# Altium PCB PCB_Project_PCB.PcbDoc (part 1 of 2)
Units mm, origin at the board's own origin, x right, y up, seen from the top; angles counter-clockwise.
Board outline 177.8 x 50.8 mm, 4 copper layers (Top Layer, Signal Layer 1, Signal Layer 2, Bottom Layer), stack 1.016 mm thick; 119 components, 90 nets, 392 pads, 439 vias.
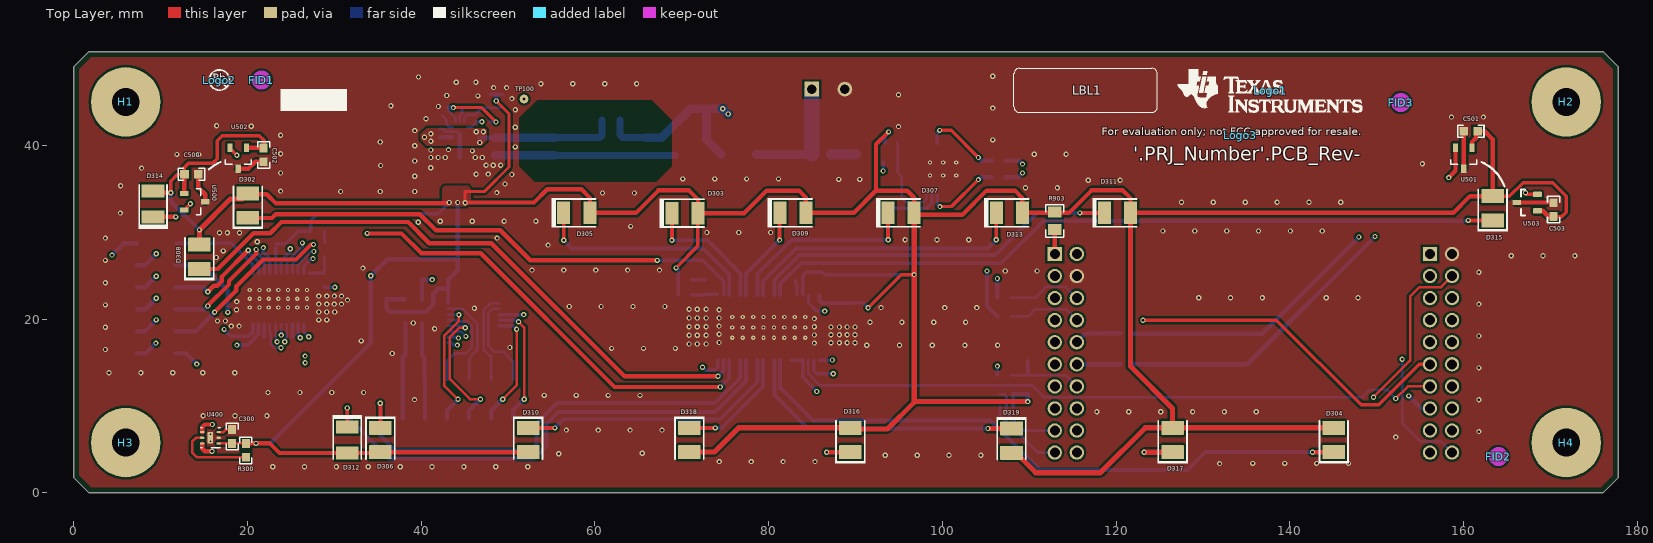
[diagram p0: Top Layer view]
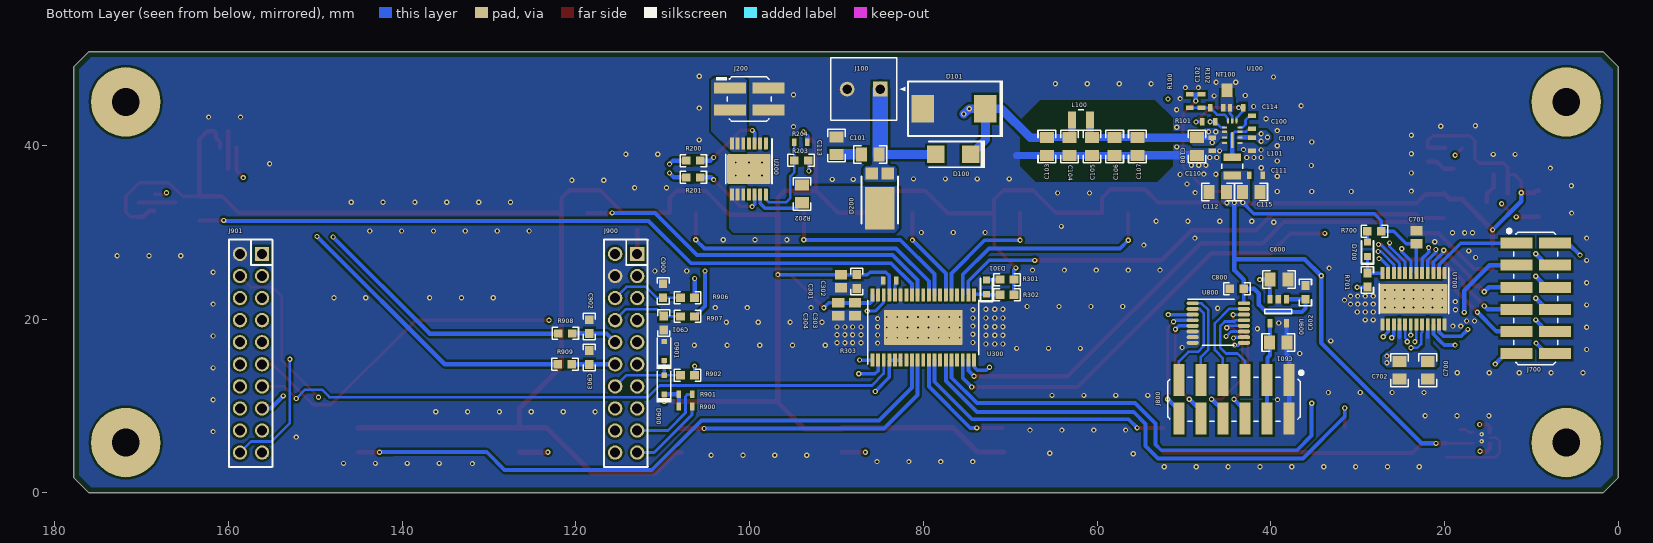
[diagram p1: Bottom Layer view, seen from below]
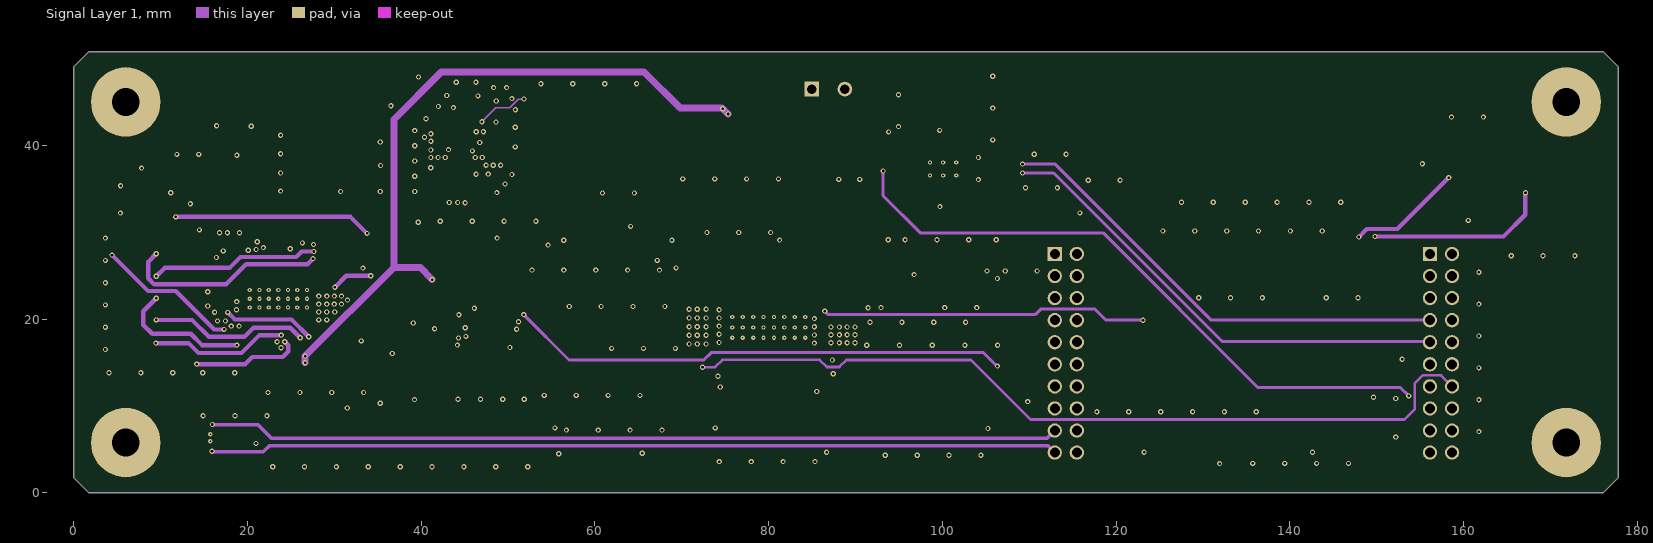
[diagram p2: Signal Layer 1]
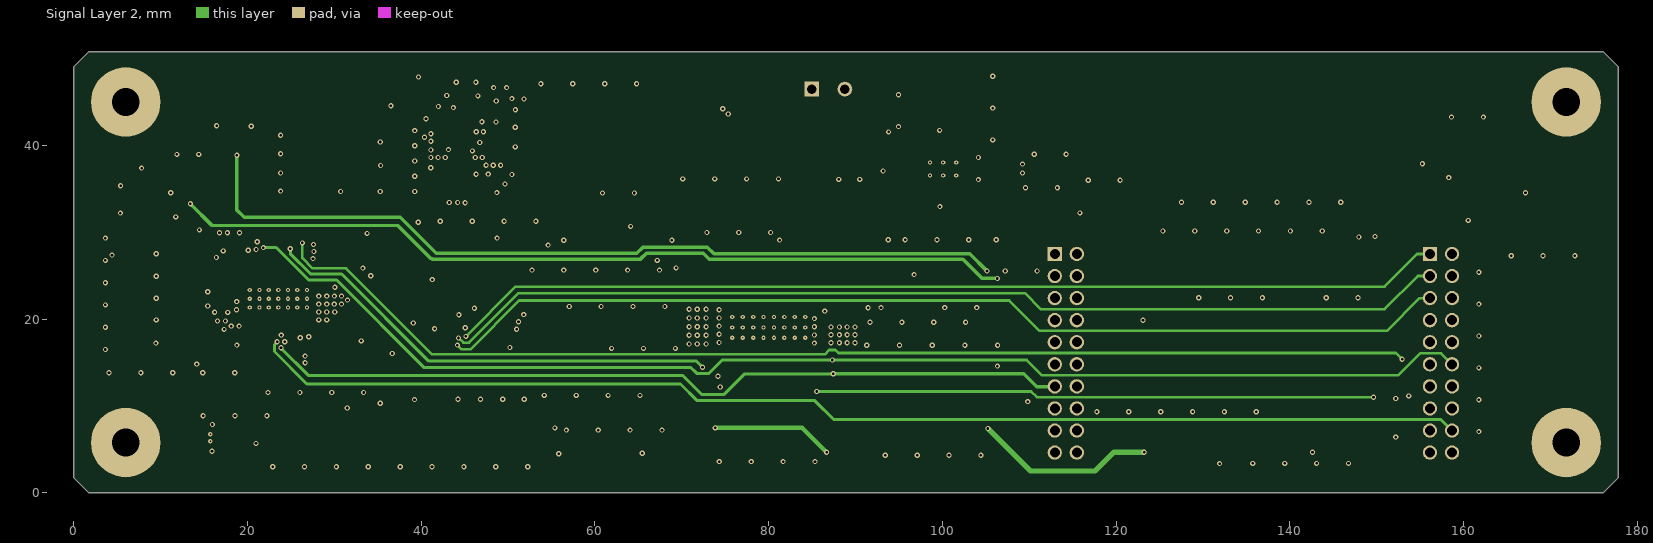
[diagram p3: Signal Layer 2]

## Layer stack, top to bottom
Top Solder: solder mask 0.0102, Solder Resist, Dk 3.5
Top Layer: signal copper 0.0356
Dielectric 2: prepreg 0.127, FR-4, Dk 4.2
Signal Layer 1: signal copper 0.0356
Dielectric 3: core 0.6198, FR-4, Dk 4.2
Signal Layer 2: signal copper 0.0356
Dielectric1: prepreg 0.127, FR-4, Dk 4.2
Bottom Layer: signal copper 0.0356
Bottom Solder: solder mask 0.0102, Solder Resist, Dk 3.5

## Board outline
0,1.778 0,49.022 1.778,50.8 176.022,50.8 177.8,49.022 177.8,1.778 176.022,0 1.778,0

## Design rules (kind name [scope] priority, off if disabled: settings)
AcuteAngle [All] p1: minimum=4.50000000000000E+0001 checktracksonly=FALSE
AssemblyTestPointUsage [All] p1: valid=2
BoardOutlineClearance BoardOutlineClearance_MountingHoles [OnCopper and InComponentClass('Mounting Holes')] p1: gap=1.016 ignorepadtopadclearanceinfootprint=FALSE
BoardOutlineClearance BoardOutlineClearance_Poly [OnCopper and IsPoly] p2: gap=0.635 ignorepadtopadclearanceinfootprint=FALSE
BoardOutlineClearance [OnCopper and Not InComponentClass('Logo') and not InComponentClass('FiducialMark') and not InRegion(1000,500,4000,800) and not InPoly] p3: gap=1.905 ignorepadtopadclearanceinfootprint=FALSE
Clearance "Stitching GND" [IsStitchingVia and InNet('GND') vs (IsVia and (Not IsStitchingVia)) Or IsPad] p1: gap=0.127 ignorepadtopadclearanceinfootprint=FALSE
Clearance Clearance_Keepouts [((IsTrack Or IsArc) And Not InPoly) And IsFree and IsKeepOut vs ((IsTrack Or IsArc) And Not InPoly) And IsFree and IsKeepOut] p2: gap=0 ignorepadtopadclearanceinfootprint=FALSE
Clearance Clearance_Poly [InPolygon] p3: gap=0.25 ignorepadtopadclearanceinfootprint=FALSE
Clearance Clearance_FiducialMark [IsKeepOut and InComponentClass('FiducialMark') vs IsPad and InComponentClass('FiducialMark')] p4: gap=0 ignorepadtopadclearanceinfootprint=FALSE
Clearance [All] p5: gap=0.2 ignorepadtopadclearanceinfootprint=FALSE except(0: Arc-Hole Track-Hole SMDPad-Hole THPad-Hole Via-Hole Fill-Hole Poly-Hole Region-Hole Text-Hole)
ComponentClearance ComponentClearance_MountingHoles_FiducialMarks [InComponentClass('Mounting Holes') vs InComponentClass('FiducialMark')] p1: gap=1.27 collisioncheckmode=3 verticalgap=0.254 showdistances=FALSE
ComponentClearance ComponentClearance_Shunt [InComponentClass('Header') vs InComponentClass('Shunt')] p2: gap=0 collisioncheckmode=3 verticalgap=0 showdistances=FALSE
ComponentClearance ComponentClearance_Logo [InComponentClass('Logo')] p3: gap=1.27 collisioncheckmode=3 verticalgap=0.254 showdistances=FALSE
ComponentClearance ComponentClearance_ScrewToNut [(HasFootprint('NY PMS 440 0025 PH')) vs (HasFootprint('Keystone_1902C'))] p4: gap=0.127 collisioncheckmode=3 verticalgap=0.254 showdistances=FALSE
ComponentClearance ComponentClearance_MountingHoles [InComponentClass('Mounting Holes')] p5: gap=6.35 collisioncheckmode=3 verticalgap=2540 showdistances=FALSE
ComponentClearance ComponentClearance_SmallPassives [HasFootprint('0201*') or HasFootprint('0402*') or HasFootprint('0508') or HasFootprint('0603*') or HasFootprint('0612') or HasFootprint('0805*') or HasFootprint('0815*') or HasFootprint('0830*') or HasFootprint('1206*') or HasFootprint('1210*') or HasFootprint('1808*') or HasFootprint('1812*') or HasFootprint('1825*') or HasFootprint('2010*') or HasFootprint('2220*') or HasFootprint('2225*') or HasFootprint('2512*') or HasFootprint('2728*') or HasFootprint('3518*') vs HasFootprint('0201*') or HasFootprint('0402*') or HasFootprint('0508') or HasFootprint('0603*') or HasFootprint('0612') or HasFootprint('0805*') or HasFootprint('0815*') or HasFootprint('0830*') or HasFootprint('1206*') or HasFootprint('1210*') or HasFootprint('1808*') or HasFootprint('1812*') or HasFootprint('1825*') or HasFootprint('2010*') or HasFootprint('2220*') or HasFootprint('2225*') or HasFootprint('2512*') or HasFootprint('2728*') or HasFootprint('3518*')] p6: gap=0.38 collisioncheckmode=3 verticalgap=0.254 showdistances=FALSE
ComponentClearance ComponentClearance_THtoSMT [IsThruComponent vs IsSMTComponent] p7: gap=1.016 collisioncheckmode=3 verticalgap=0.762 showdistances=FALSE
ComponentClearance ComponentClearance_THtoTH [IsThruComponent vs IsThruComponent] p8: gap=0.762 collisioncheckmode=3 verticalgap=0.762 showdistances=FALSE
ComponentClearance [All] p9: gap=0.762 collisioncheckmode=3 verticalgap=0.254 showdistances=FALSE
DiffPairsRouting [All] p1: maxlimit=2.54 minlimit=0.254 mostfreqgap=0.254 toplayer_minwidth=0.381 toplayer_maxwidth=0.381 toplayer_prefwidth=0.381 midlayer1_minwidth=0.381 midlayer1_maxwidth=0.381 midlayer1_prefwidth=0.381 midlayer2_minwidth=0.381 midlayer2_maxwidth=0.381 midlayer2_prefwidth=0.381 bottomlayer_minwidth=0.381 bottomlayer_maxwidth=0.381 bottomlayer_prefwidth=0.381 maxuncoupledlength=25.4
FabricationTestPointUsage TestPointUsage [All] p1: valid=2 allowmultiple=FALSE
FabricationTestpoint Testpoint [All] p1: side=3 testpointundercomponent=TRUE minsize=1.016 maxsize=2.54 preferedsize=1.524 minholesize=0 maxholesize=1.016 preferedholesize=0.813 testpointgrid=0.025 allowsidetop=TRUE allowsidebottom=TRUE usegrid=TRUE gridtolerance=0
FanoutControl Fanout_LCC [IsLCC] p1: bgadir=Out bgaviamode=Centered fanoutstyle=Auto fanoutdirection=Alternating viagrid=0.025 // Fanout_LCC (Default Rule)
FanoutControl Fanout_BGA [IsBGA] p2: bgadir=Out bgaviamode=Centered fanoutstyle=Auto fanoutdirection=Alternating viagrid=0.025 // Fanout_BGA (Default Rule)
FanoutControl Fanout_Default [All] p4: bgadir=Out bgaviamode=Centered fanoutstyle=Auto fanoutdirection=Alternating viagrid=0.025 // Fanout_Default (Default Rule)
FanoutControl Fanout_Small [(CompPinCount < 5)] p5: bgadir=Out bgaviamode=Centered fanoutstyle=Auto fanoutdirection=OutThenIn viagrid=0.025 // Fanout_Small (Default Rule)
HoleSize [All] p1: absolutevalues=TRUE maxlimit=6.375 minlimit=0.2 maxpercent=80.000 minpercent=20.000
MinimumAnnularRing MinimumAnnularRing_ThermalPadVias [IsVia and InAnyComponent] p1: minimumring=0.15
MinimumAnnularRing [All] p2: minimumring=0.15
MinimumSolderMaskSliver MinimumSolderMaskSliver_Logo [InComponentClass('Logo') vs InComponentClass('Logo')] p1 off: minsoldermaskwidth=0.018
MinimumSolderMaskSliver [All] p2 off: minsoldermaskwidth=0.1
PlaneClearance [All] p1: clearance=0.3
PlaneConnect [All] p1: planeconnectstyle=Relief reliefexpansion=0.254 reliefentries=4 reliefconductorwidth=0.254 reliefairgap=0.254
PolygonConnect [All] p1: connectstyle=Direct reliefconductorwidth=0.254 reliefentries=4 polygonreliefangle="90 Angle" airgapwidth=0.254
RoutingVias ThermalPadVias [IsVia and InAnyComponent] p1: holewidth=0.2 width=0.5 viastyle="Through Hole" minholewidth=0.2 minwidth=0.5 maxholewidth=0.33 maxwidth=0.6
RoutingVias [All] p2: holewidth=0.406 width=0.864 viastyle="Through Hole" minholewidth=0.2 minwidth=0.6 maxholewidth=1.016 maxwidth=1.651
SilkToBoardRegionClearance [Not ((IsComment or IsDesignator) And (Hide <> 'False')) and not InRegion(1000,500,4000,800)] p1:
SilkToSilkClearance SilkToSilkClearance_Pb-FreeLogo [(HasFootprint('Pb-Free_Overlay_Medium') OR HasFootprint('Pb-Free_Overlay_Small')) vs (HasFootprint('Pb-Free_Overlay_Medium') OR HasFootprint('Pb-Free_Overlay_Small'))] p1 off: silktosilkclearance=0
SilkToSilkClearance [All] p2 off: silktosilkclearance=0.1
SilkToSolderMaskClearance SilkToComponentPadClearance [(IsPad or IsFill or IsRegion) and InAnycomponent] p1 off: minsilkscreentomaskgap=0.127 clearancetoexposedcopper=TRUE
SilkToSolderMaskClearance "Silk to Solder Mask Opening" [All] p2 off: minsilkscreentomaskgap=0.102 clearancetoexposedcopper=FALSE
SolderMaskExpansion [All] p1: expansion=0.05
Width [All] p1: maxlimit=2.54 minlimit=0.15 preferedwidth=0.254 checkconnectedcopper=TRUE
14 further rules are at their usual default settings.

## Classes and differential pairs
component class Label: LBL1
component class AssemblyNote: ZZ1 ZZ2 ZZ3 ZZ4
component class FiducialMark: FID1 FID2 FID3
component class HVAC_HMI_EVM_Hardware: FID1 FID2 FID3 H1 H2 H3 H4 LBL1 Logo1 Logo2 Logo3 ZZ1 ZZ2 ZZ3 ZZ4
component class Logo: Logo1
component class "Mounting Holes": H1 H2 H3 H4
component class HVA_HMI_p1: C100 C101 C102 C103 C104 C105 C106 C107 C108 C109 C110 C111 C112 C113 C114 C115 C300 C301 C302 C303 C304 C500 C501 C502 C503 C? D100 D101 D200 D301 D302 D303 D304 D305 D306 D307 D308 D309 D310 D311 D312 D313 D314 D315 D316 D317 D318 D319 J100 J200 L100 L101 NT100 R100 R101 R102 R200 R201 R202 R203 R204 R300 R301 R302 R303 TP100 U100 U200 U300 U400 U500 U501 U502 U503
component class HVA_HMI_p2: C600 C601 C602 C700 C701 C702 C800 C900 C901 C902 C903 D700 D900 D901 J300 J301 J700 J800 J900 J901 J? R700 R701 R900 R901 R902 R903 R906 R907 R908 R909 U600 U700 U800
component class Header: J200 J700 J800

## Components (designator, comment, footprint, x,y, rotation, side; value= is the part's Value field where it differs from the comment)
C100 "CGA3E2X7R1H104K080AA" 0603S 42.164,42.672 r90 bottom value=0.1uF
C101 "CGA4J2X7R2A473K125AA" 0805_HV 86.106,38.964 r0 bottom value=0.047uF
C102 "CGA3E2C0G1H100D080AA" 0603S 47.981,45.11 r270 bottom value=10pF
C103 "CGA4J3X7R1H225K125AB" 0805_HV 65.786,39.878 r270 bottom value=2.2uF
C104 "CGA4J3X7R1H225K125AB" 0805_HV 63.182,39.878 r270 bottom value=2.2uF
C105 "CGA4J3X7R1H225K125AB" 0805_HV 60.579,39.878 r270 bottom value=2.2uF
C106 "CGA4J3X7R1H225K125AB" 0805_HV 57.975,39.878 r270 bottom value=2.2uF
C107 "GRT21BR61H475KE13L" 0805_HV 55.372,39.878 r270 bottom value=4.7uF
C108 "GRT21BR61H475KE13L" 0805_HV 48.514,39.878 r270 bottom value=4.7uF
C109 "GCM188R71H224KA64D" 0603S 42.164,40.132 r270 bottom value=0.22uF
C110 "GCM188R71H224KA64D" 0603S 46.736,40.132 r270 bottom value=0.22uF
C111 "C0603C103J3GECAUTO" 0603S 41.707,36.576 r180 bottom value=0.01uF
C112 "CGA4J1X7R1E475K125AC" 0805_HV 46.101,34.646 r0 bottom value=4.7uF
C113 "CGA4J2X7R2A473K125AA" 0805_HV 90,39.98 r90 bottom value=0.047uF
C114 "CGA3E1X7R1C105K080AC" 0603S 43.942,44.348 r180 bottom value=1uF
C115 "CGA4J1X7R1E475K125AC" 0805_HV 42.266,34.646 r180 bottom value=4.7uF
C300 "C0603C103J3GECAUTO" 0603 18.237,6.5 r90 top value=0.01uF
C301 "CGA4J1X7R1E475K125AC" 0805L 89.484,24.384 r270 bottom value=4.7uF
C302 "CGJ3E2X7R1C104K080AA" 0603 87.655,24.333 r270 bottom value=0.1uF
C303 "CGA4J1X7R1E475K125AC" 0805L 87.867,21.133 r270 bottom value=4.7uF
C304 "CGA4J1X7R1E475K125AC" 0805L 89.797,21.133 r270 bottom value=4.7uF
C500 "CGJ3E2X7R1C104K080AA" 0603 13.564,36.678 r0 top value=0.1uF
C501 "CGJ3E2X7R1C104K080AA" 0603 160.807,41.631 r180 top value=0.1uF
C502 "CGJ3E2X7R1C104K080AA" 0603 21.869,38.913 r270 top value=0.1uF
C503 "CGJ3E2X7R1C104K080AA" 0603 170.332,32.614 r90 top value=0.1uF
C600 "GCM21BR71H104KA37K" 0805_HV 39.065,24.562 r180 bottom value=0.1uF
C601 "GCM21BR71H104KA37K" 0805_HV 39.141,17.323 r180 bottom value=0.1uF
C602 "CGJ3E2X7R1C104K080AA" 0603 36.017,23.089 r90 bottom value=0.1uF
C700 "GRT21BR61H475KE13L" 0805_HV 21.946,14.122 r270 bottom value=4.7uF
C701 "CGA4J1X7R1E475K125AC" 0805L 23.241,29.439 r90 bottom value=4.7uF
C702 "GRT21BR61H475KE13L" 0805_HV 25.197,14.122 r270 bottom value=4.7uF
C800 "CGJ3E2X7R1C104K080AA" 0603 43.917,23.495 r0 bottom value=0.1uF
C900 "CGA3E2C0G1H221J080AA" 0603 109.957,23.266 r90 bottom value=220pF
C901 "CGA3E2C0G1H221J080AA" 0603 109.88,19.558 r270 bottom value=220pF
C902 "CGA3E2C0G1H221J080AA" 0603 118.44,19.152 r90 bottom value=220pF
C903 "CGA3E2C0G1H221J080AA" 0603 118.44,15.596 r90 bottom value=220pF
D100 "B360AM-13-F" SMA 76.556,38.964 r0 bottom value=60V
D101 "TPSMD26A" SMC_265 76.454,44.221 r0 bottom value=26V
D200 "PDS5100HQ-13" POWERDI5 85.014,34.773 r270 bottom value=100V
D301 "APT1608SYCK" APT1608_Yellow 72.733,23.698 r270 bottom value=Yellow
D302 "VLMR334BACB-GS08" VLMR334_Red 20.066,33.074 r270 top value=Red
D303 "LW T67C-S2V1-5K8L-Z" LW_T67C_White 70.358,32.207 r270 top value=White
D304 "VLMR334BACB-GS08" VLMR334_Red 145.034,6.096 r270 top value=Red
D305 "LW T67C-S2V1-5K8L-Z" LW_T67C_White 57.912,32.233 r270 top value=White
D306 "VLMR334BACB-GS08" VLMR334_Red 35.306,6.096 r90 top value=Red
D307 "LW T67C-S2V1-5K8L-Z" LW_T67C_White 95.25,32.233 r270 top value=White
D308 "VLMR334BACB-GS08" VLMR334_Red 14.478,27.178 r270 top value=Red
D309 "LW T67C-S2V1-5K8L-Z" LW_T67C_White 82.779,32.233 r270 top value=White
D310 "VLMR334BACB-GS08" VLMR334_Red 52.324,6.096 r90 top value=Red
D311 "LW T67C-S2V1-5K8L-Z" LW_T67C_White 120.142,32.233 r270 top value=White
D312 "LY T67K-J2M1-26-Z" LY_T67K_Yellow 31.496,6.096 r180 top value=Yellow
D313 "LW T67C-S2V1-5K8L-Z" LW_T67C_White 107.696,32.233 r270 top value=White
D314 "LB T673-L2P1-25-Z" LB_T673_Blue 9.144,33.274 r0 top value=Blue
D315 "VLMR334BACB-GS08" VLMR334_Red 163.322,32.766 r270 top value=Red
D316 "VLMR334BACB-GS08" VLMR334_Red 89.408,6.096 r270 top value=Red
D317 "VLMR334BACB-GS08" VLMR334_Red 126.492,6.096 r270 top value=Red
D318 "VLMR334BACB-GS08" VLMR334_Red 70.866,6.096 r90 top value=Red
D319 "VLMR334BACB-GS08" VLMR334_Red 107.95,6.02 r90 top value=Red
D700 "APT1608SYCK" APT1608_Yellow 28.88,28.042 r270 bottom value=Yellow
D900 "BAS316,115" SOD-323 109.83,12.454 r90 bottom value=100V
D901 "BAS316,115" SOD-323 109.83,16.34 r90 bottom value=100V
FID1 "Fiducial" Fiducial10-20 21.615,47.523 r0 top
FID2 "Fiducial" Fiducial10-20 163.982,4.191 r0 top
FID3 "Fiducial" Fiducial10-20 152.756,44.933 r0 top
H1 "NY PMS 440 0025 PH" "NY PMS 440 0025 PH"#1 5.08,44.958 r0 top locked
H2 "NY PMS 440 0025 PH" "NY PMS 440 0025 PH"#2 171.958,44.958 r0 top locked
H3 "NY PMS 440 0025 PH" "NY PMS 440 0025 PH"#3 5.08,5.08 r0 top locked
H4 "NY PMS 440 0025 PH" "NY PMS 440 0025 PH"#4 171.958,5.08 r0 top locked
J100 "1727010" PhoenixConact_1727010 86.868,46.482 r0 bottom
J200 "15-91-2040" Molex_15-91-2040 100.051,45.339 r270 bottom
J700 "15912120" MOLEX_0015912120 9.525,22.403 r270 bottom
J800 "15912120" MOLEX_0015912120 44.247,10.795 r0 bottom
J900 "66953-010LF" FCI_66953-010LF 114.198,16.078 r90 bottom
J901 "66953-010LF" FCI_66953-010LF 157.378,16.078 r90 bottom
L100 "DFE252012PD-R68M" DFE252012P 61.849,42.926 r180 bottom value=680nH
L101 "DFE252012PD-4R7M" DFE252012P 44.45,37.592 r270 bottom value=4.7uH
LBL1 "THT-14-423-10" Label_650x200 116.484,46.33 r0 top
Logo1 "Texas Instruments" TI_Stacked_Overlay_Small 137.719,46.279 r0 top
Logo2 "Pb-Free Symbol" Pb-Free_Overlay_Small 16.789,47.523 r0 top
Logo3 "FCC disclaimer" FCC_disclaimer 134.264,41.199 r0 top
NT100 "Net-Tie" Net-Tie_50milWide_30milLong 45.06,46.355 r90 bottom net-tie
R100 "ERJ-3GEYJ104V" 0603S 49.327,45.11 r90 bottom value=100k
R101 "CRCW060310K0JNEA" 0603S 47.142,42.723 r0 bottom value=10k
R102 "CRCW060343K2FKEA" 0603S 46.228,44.348 r0 bottom value=43.2k
R200 "ERJ-3GEYJ472V" 0603 106.477,38.252 r0 bottom value=4.7k
R201 "ERJ-3GEYJ472V" 0603 106.477,36.322 r0 bottom value=4.7k
R202 "RR1220P-621-D" 0805_HV 93.98,34.417 r270 bottom value=620
R203 "ERJ-3GEYJ472V" 0603 94.056,38.278 r180 bottom value=4.7k
R204 "ERJ-3GEYJ472V" 0603S 94.107,40.361 r180 bottom value=4.7k
R300 "CRCW060310K0JNEA" 0603 19.837,4.902 r90 top value=10k
R301 "RCA06031K00JNEA" 0603 70.371,24.562 r180 bottom value=1.0k
R302 "ERJ-3GEYJ472V" 0603 70.371,22.809 r0 bottom value=4.7k
R303 "CRCW06032R43FKEA" 0603S 83.871,24.46 r180 bottom value=2.43
R700 "RCA06031K00JNEA" 0603 28.092,30.124 r180 bottom value=1.0k
R701 "ERJ-3GEYJ472V" 0603 28.88,24.511 r90 bottom value=4.7k
R900 "ERJ-3GEYJ472V" 0603S 107.366,9.957 r0 bottom value=4.7k
R901 "ERJ-3GEYJ472V" 0603S 107.366,11.354 r0 bottom value=4.7k
R902 "CRCW0603100RJNEA" 0603 107.137,13.546 r180 bottom value=100
R903 "CRCW08050000Z0EA" 0805_HV 112.928,31.318 r270 top value=0
R906 "RCA06031K00JNEA" 0603 107.137,22.479 r180 bottom value=1.0k
R907 "RCA06031K00JNEA" 0603 107.137,20.32 r180 bottom value=1.0k
R908 "RCA06031K00JNEA" 0603 121.209,18.364 r0 bottom value=1.0k
R909 "RCA06031K00JNEA" 0603 121.26,14.808 r0 bottom value=1.0k
TP100 "TP_SM_1MM" TP_SM_1MM 51.841,45.339 r90 top
U100 "LMR36006AQRNXRQ1" RNX0012B 44.45,41.402 r0 bottom
U200 "TPS1H100AQPWPRQ1" PWP0014C_N 100.076,37.287 r270 bottom
U300 "TLC6C5716QDAPRQ1" DAP0038E 80.01,19.05 r90 bottom
U400 "OPT3001IDNPRQ1" DNP0006A 15.748,6.35 r180 top
U500 "DRV5055A1QDBZT" DBZ0003A_N 13.945,33.528 r0 top
U501 "DRV5055A1QDBZT" DBZ0003A_N 160,38.532 r270 top
U502 "DRV5055A1QDBZT" DBZ0003A_N 18.948,38.532 r270 top
U503 "DRV5055A1QDBZT" DBZ0003A_N 167.284,33.426 r180 top
U600 "TPS7B4250QDBVRQ1" DBV0005A_N 39.141,20.904 r270 bottom
U700 "DRV8912PWPRQ1" PWP0024J_N 23.571,22.352 r270 bottom
U800 "SN74LV4051AQPWRQ1" PW0016A_N 46.05,19.558 r180 bottom
ZZ1 "This Assembly Note is for PCB labels only" AssemblyNoteLabel 197.866,5.918 r90 top
ZZ2 "These assemblies are ESD sensitive, ESD precautions shall be observed." AssemblyNote 191.821,131.013 r90 top
ZZ3 "These assemblies must be clean and free from flux and all contaminants. Use of no clean flux is not acceptable." AssemblyNote 185.801,131.013 r90 top
ZZ4 "These assemblies must comply with workmanship standards IPC-A-610 Class 2, unless otherwise specified." AssemblyNote 179.756,131.013 r90 top

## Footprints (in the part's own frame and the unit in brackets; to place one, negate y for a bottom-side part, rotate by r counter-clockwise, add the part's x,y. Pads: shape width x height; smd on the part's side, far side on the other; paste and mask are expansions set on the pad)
0603 [mm] "0603 from SM-752 data"
  rect 1x0.95 smd: 1(-0.8,0) 2(0.8,0)
  silkscreen extent -1.52,-0.69 1.52,0.69, body extent -0.87,-0.47 0.87,0.47, height 1
0603S [mil]
  rect 20x35 smd: 1(-30,0) 2(30,0)
  body extent -34,-19 34,19, height 39
0805_HV [mil] "0805 with 30mil clearance between pads"
  rect 50x63 smd: 1(-40,0) 2(40,0)
  silkscreen extent -74,-40 74,40, body extent -43,-29 43,29, height 57
0805L [mm] "0805 from SM-752 data"
  rect 1.1x1.4 smd: 1(-0.75,0) 2(0.75,0)
  body extent -1.1,-0.72 1.1,0.72, height 1.45
APT1608_Yellow [mm] "SMD, 2-Leads, Body 0.8x1.6mm"
  rect 0.8x0.8 smd: 1(-0.825,0) 2(0.825,0)
  silkscreen extent -1,-0.7 1.8,0.7, body extent -0.8,-0.4 0.81,0.4, height 0.76
AssemblyNote [mm] "Assembly Note"
AssemblyNoteLabel [mm] "Assembly Note for PCB Labels"
DAP0038E [mm] "SOP, 38-Leads, Body 6.1x12.5mm, Pitch 0.65mm"
  rrect22% 1.5x0.45 smd: 1(-3.75,5.85) 2(-3.75,5.2) 3(-3.75,4.55) 4(-3.75,3.9) 5(-3.75,3.25) 6(-3.75,2.6) 7(-3.75,1.95) 8(-3.75,1.3) 9(-3.75,0.65) 10(-3.75,0) 11(-3.75,-0.65) 12(-3.75,-1.3) 13(-3.75,-1.95) 14(-3.75,-2.6) 15(-3.75,-3.25) 16(-3.75,-3.9) 17(-3.75,-4.55) 18(-3.75,-5.2) 19(-3.75,-5.85) 20(3.75,-5.85) 21(3.75,-5.2) 22(3.75,-4.55) 23(3.75,-3.9) 24(3.75,-3.25) 25(3.75,-2.6) 26(3.75,-1.95) 27(3.75,-1.3) 28(3.75,-0.65) 29(3.75,0) 30(3.75,0.65) 31(3.75,1.3) 32(3.75,1.95) 33(3.75,2.6) 34(3.75,3.25) 35(3.75,3.9) 36(3.75,4.55) 37(3.75,5.2) 38(3.75,5.85)
  rrect2% 4x9 smd paste-9 mask-4: 39(0,0)
  rrect12% 0.8x1.178 on Bottom Paste: ""(0,-2.059) ""(0,2.059)
  rrect5% 1.94x2.54 on Bottom Paste: ""(0,0)
  silkscreen extent -4.2,-6.4 3.1,6.4, body extent -4.05,-6.25 4.05,6.25, height 1.13
DBV0005A_N [mm] "SOT23, 5-Leads, Body 2.9x1.6mm, Pitch 0.95mm, Lead Span 2.8mm, IPC Medium Density"
  rrect17% 1x0.6 smd: 1(-1.375,0.95) 2(-1.375,0) 3(-1.375,-0.95) 4(1.375,-0.95) 5(1.375,0.95)
  silkscreen extent -0.25,-1.55 0.25,1.55, body extent -1.42,-1.46 1.42,1.46, height 1.09
DBZ0003A_N [mm] "SOT23, 3-Leads, Body 2.9x1.3mm, Pitch 0.95mm, Lead Span 2.4mm, IPC Medium Density"
  rrect17% 1x0.6 smd: 1(-1.2,0.95) 2(-1.2,-0.95) 3(1.2,0)
  silkscreen extent 0.2,-1.5 0.7,1.5, body extent -1.26,-1.46 1.26,1.46, height 0.98
DFE252012P [mm] "TOKO, Pad sizes increased as per request"
  rect 0.9x2 smd: 1(-1.05,0) 2(1.05,0)
  silkscreen extent -0.3,-1.2 0.3,1.2, body extent -1.35,-1.1 1.35,1.1, height 1.2
DNP0006A [mm] "DFN-6 2x2mm"
  oval 0.5x0.25 smd: 1(-0.95,0.65) 2(-0.95,0) 3(-0.95,-0.655) 4(0.95,-0.65) 5(0.95,0) 6(0.95,0.65)
  rect 0.65x1.35 smd paste-0.5: 7(0,0)
  silkscreen extent -1.12,-1.15 1.12,1.15, body extent -1,-1 1,1, height 0.64
FCC_disclaimer [mm]
FCI_66953-010LF [mm] "FCI"
  rect 1.65x1.65 hole 1.15: 1(11.43,-1.27)
  round 1.65 hole 1.15: 2(11.43,1.27) 3(8.89,-1.27) 4(8.89,1.27) 5(6.35,-1.27) 6(6.35,1.27) 7(3.81,-1.27) 8(3.81,1.27) 9(1.27,-1.27) 10(1.27,1.27) 11(-1.27,-1.27) 12(-1.27,1.27) 13(-3.81,-1.27) 14(-3.81,1.27) 15(-6.35,-1.27) 16(-6.35,1.27) 17(-8.89,-1.27) 18(-8.89,1.27) 19(-11.43,-1.27) 20(-11.43,1.27)
  silkscreen extent -13.08,-2.46 13.08,2.54, body extent -13,-2.51 13,2.54, height 8.59
Fiducial10-20 [mm]
  round 1 smd mask+0.5: 1(0,0)
  Top Layer keep-out circle w1.178: c0,0 r0.5
Label_650x200 [mil] "Thermal Transfer Label"
  round 1 on Mech13: 0(0,0)
  silkscreen extent -325,-100 325,100, body extent -325,-100 325,100, height 1
LB_T673_Blue [mm] "SMD, 2-Leads, Body 3.2x2.8mm"
  rect 2.6x1.5 smd mask+0: 1(0,1.5) 2(0,-1.5)
  silkscreen extent -1.7,-2.9 1.7,2.2, body extent -1.5,-1.85 1.5,1.85, height 2.1
LW_T67C_White [mm] "SMD, 2-Leads, Body 3.2x2.8mm"
  rect 2.6x1.5 smd mask+0: 1(0,1.5) 2(0,-1.5)
  silkscreen extent -1.7,-2.9 1.7,2.2, body extent -1.5,-1.85 1.5,1.85, height 2.1
LY_T67K_Yellow [mm] "SMD, 2-Leads, Body 3.2x2.8mm"
  rect 2.6x1.5 smd mask+0: 1(0,1.5) 2(0,-1.5)
  silkscreen extent -1.7,-2.9 1.7,2.2, body extent -1.5,-1.85 1.5,1.85, height 2.1
Molex_15-91-2040 [mm] "Molex"
  rect 1.27x3.68 smd: 1(-1.27,-2.222) 2(-1.27,2.223) 3(1.27,-2.223) 4(1.27,2.222)
  silkscreen extent -2.54,-3.81 2.54,2.54, body extent -2.54,-3.49 2.54,3.49, height 9.65
MOLEX_0015912120 [mm] "MOLEX"
  rect 1.27x3.68 smd: 1(-6.35,-2.222) 2(-6.35,2.223) 3(-3.81,-2.222) 4(-3.81,2.223) 5(-1.27,-2.222) 6(-1.27,2.223) 7(1.27,-2.223) 8(1.27,2.222) 9(3.81,-2.223) 10(3.81,2.222) 11(6.35,-2.223) 12(6.35,2.222)
  silkscreen extent -7.95,-3.25 7.62,2.54, body extent -7.62,-3.49 7.62,3.49, height 9.65
Net-Tie_50milWide_30milLong [mil] "50mil net tie, no solder mask opening, no solder paste"
  rect 30x50 smd paste-20 mask-20: 1(-15,0) 2(15,0)
"NY PMS 440 0025 PH"#1 [mm] "4-40 nylon screw and mounting hole"
  round 8 hole 3.2: 1(0.92,0.042)
  body extent -3.3,-3.3 3.3,3.3, height 2.69
"NY PMS 440 0025 PH"#2 [mm] "4-40 nylon screw and mounting hole"
  round 8 hole 3.2: 1(-0.158,0.042)
  body extent -3.3,-3.3 3.3,3.3, height 2.69
"NY PMS 440 0025 PH"#3 [mm] "4-40 nylon screw and mounting hole"
  round 8 hole 3.2: 1(0.92,0.72)
  body extent -3.3,-3.3 3.3,3.3, height 2.69
"NY PMS 440 0025 PH"#4 [mm] "4-40 nylon screw and mounting hole"
  round 8 hole 3.2: 1(-0.158,0.72)
  body extent -3.3,-3.3 3.3,3.3, height 2.69
Pb-Free_Overlay_Small [mm]
  silkscreen extent -1.16,-1.17 1.17,1.17
PhoenixConact_1727010 [mm]
  rect 1.7x1.7 hole 1.1: 1(-1.905,0)
  round 1.7 hole 1.1: 2(1.905,0)
  silkscreen extent -4.8,-3.6 3.81,3.6, body extent -3.81,-3.6 3.81,3.7, height 8.52
POWERDI5 [mm] "Diodes Inc recommended land pattern, ap02001.pdf rev 60"
  rect 1.4x1.39 smd: 1(-1.991,0.92) 2(-1.991,-0.92)
  rect 4.86x3.36 smd: 3(1.991,0)
  silkscreen extent -1.7,-2.1 3.8,2.1, body extent -2.27,-2.02 4.33,2.03, height 1.17
PW0016A_N [mm] "TSOP, 16-Leads, Body 5x4.4mm, Pitch 0.65mm, IPC Medium Density"
  oval 1.4x0.45 smd: 1(-2.95,2.275) 2(-2.95,1.625) 3(-2.95,0.975) 4(-2.95,0.325) 5(-2.95,-0.325) 6(-2.95,-0.975) 7(-2.95,-1.625) 8(-2.95,-2.275) 9(2.95,-2.275) 10(2.95,-1.625) 11(2.95,-0.975) 12(2.95,-0.325) 13(2.95,0.325) 14(2.95,0.975) 15(2.95,1.625) 16(2.95,2.275)
  silkscreen extent -3.5,-2.55 1.85,2.75, body extent -3.21,-2.5 3.21,2.5, height 1
PWP0014C_N [mm] "TSOP, 14-Leads, Body 5x4.4mm, Pitch 0.65mm, Thermal Pad 3x3 mm, IPC Medium Density"
  rrect22% 1.4x0.45 smd: 1(-2.95,1.95) 2(-2.95,1.3) 3(-2.95,0.65) 4(-2.95,0) 5(-2.95,-0.65) 6(-2.95,-1.3) 7(-2.95,-1.95) 8(2.95,-1.95) 9(2.95,-1.3) 10(2.95,-0.65) 11(2.95,0) 12(2.95,0.65) 13(2.95,1.3) 14(2.95,1.95)
  rrect6% 3.4x5 smd paste-2 mask-2: 15(0,0)
  rrect4% 2.46x2.31 on Bottom Paste: 15(0,0)
  rrect4% 2.46x2.31 on Bottom Solder: 15(0,0)
  silkscreen extent -3.47,-2.65 1.7,2.65, body extent -3.21,-2.5 3.21,2.5, height 1
PWP0024J_N [mm] "TSOP, 24-Leads, Body 7.9x4.5mm (max), Pitch 0.65mm, IPC Medium Density"
  rrect22% 1.4x0.45 smd: 1(-2.95,3.575) 2(-2.95,2.925) 3(-2.95,2.275) 4(-2.95,1.625) 5(-2.95,0.975) 6(-2.95,0.325) 7(-2.95,-0.325) 8(-2.95,-0.975) 9(-2.95,-1.625) 10(-2.95,-2.275) 11(-2.95,-2.925) 12(-2.95,-3.575) 13(2.95,-3.575) 14(2.95,-2.925) 15(2.95,-2.275) 16(2.95,-1.625) 17(2.95,-0.975) 18(2.95,-0.325) 19(2.95,0.325) 20(2.95,0.975) 21(2.95,1.625) 22(2.95,2.275) 23(2.95,2.925) 24(2.95,3.575)
  rrect6% 3.4x7.8 smd paste-2 mask-2: 25(0,0)
  rrect3% 3.2x5.26 on Bottom Paste mask+0.085: 25(0,0)
  rrect3% 3.2x5.26 on Bottom Solder mask+0.085: 25(0,0)
  silkscreen extent -3.55,-3.95 1.7,4.05, body extent -3.21,-3.9 3.21,3.9, height 1.2
RNX0012B [mm] "VQFN-HR-12"
  rrect40% 0.6x0.25 smd: 1(-0.9,1.125) 2(-0.9,0.475) 3(-0.9,-0.175) 4(-0.9,-0.675) 8(0.9,-0.675) 9(0.9,-0.175) 10(0.9,0.475) 11(0.9,1.125)
  rrect40% 0.25x0.6 smd: 5(-0.5,-1.4) 6(0,-1.4) 7(0.5,-1.4)
  rrect40% 0.25x0.812 on Bottom Paste: 12(0,0.28) 12(0,1.295)
  rrect40% 0.25x1.825 smd paste-0.175: 12(0,0.788)
  body extent -1,-1.5 1,1.5, height 1
SMA [mm] "Molded Diode, 2-Leads, Body 4.3x2.6mm, IPC Medium Density, based on OnSemi component dimensions and land pattern"
  rect 2x2 smd: 1(-2,0) 2(2,0)
  silkscreen extent -3.66,-1.57 2.79,1.57, body extent -2.6,-1.3 2.6,1.3, height 2.42
SMC_265 [mm] "SMD, 2-Leads, Body 7.15x6.25mm"
  rect 2.6x3.2 smd: 1(-3.6,0) 2(3.6,0)
  silkscreen extent -5.6,-3.22 5.3,3.23, body extent -4.08,-3.13 4.08,3.13, height 2.65
SOD-323 [mm] "NXP recommended land pattern"
  rect 0.6x0.6 smd paste-0.05: 1(-1.1,0) 2(1.1,0)
  silkscreen extent -2.06,-0.86 1.53,0.86, body extent -1.3,-0.67 1.3,0.68, height 1.1
TI_Stacked_Overlay_Small [mm]
  silkscreen extent -10.63,-2.49 10.63,2.49
TP_SM_1MM [mm] "1mm Test Point, SMT"
  round 1 smd paste-0.5: 1(0,0)
VLMR334_Red [mm] "SMD, 2-Leads, Body 3x2.8mm"
  rrect6% 1.6x2.6 smd: 1(-1.4,0) 2(1.4,0)
  silkscreen extent -2.2,-1.75 2.7,1.75, body extent -1.75,-1.4 1.75,1.4, height 1.65

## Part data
C100: library part CMP-0007078-4, "CAP, CERM, 0.1 uF, 50 V, +/- 10%, X7R, AEC-Q200 Grade 1, 0603", Cap_Case=0603, Manufacturer=TDK, Supplier Part Number 1=445-5666-1-ND, TempCo=X7R, Tolerance_%=10%, Value1="0.0296 ohm", Value2=50V, ValueDisplayed=0.1uF
C101 C113: library part CMP-0007970-2, "CAP, CERM, 0.047 uF, 100 V, +/- 10%, X7R, AEC-Q200 Grade 1, 0805", Cap_Case=0805, Manufacturer=TDK, Supplier Part Number 1=445-5825-1-ND, TempCo=X7R, Tolerance_%=10%, Value1="0.049089 ohm", Value2=100V, ValueDisplayed=0.047uF
C102: library part CMP-0007069-4, "CAP, CERM, 10 pF, 50 V, +/- 5%, C0G/NP0, AEC-Q200 Grade 1, 0603", Cap_Case=0603, Manufacturer=TDK, Supplier Part Number 1=445-5628-1-ND, TempCo=C0G/NP0, Tolerance_%=5%, Value1=Unknown, Value2=50V, ValueDisplayed=10pF
C103 C104 C105 C106: library part CMP-0007977-2, "CAP, CERM, 2.2 uF, 50 V, +/- 10%, X7R, AEC-Q200 Grade 1, 0805", Cap_Case=0805, Manufacturer=TDK, Supplier Part Number 1=445-174216-1-ND, TempCo=X7R, Tolerance_%=10%, Value1="0.003288 ohm", Value2=50V, ValueDisplayed=2.2uF
C107 C108 C700 C702: library part CMP-0008380-2, "CAP, CERM, 4.7 uF, 50 V, +/- 10%, X5R, AEC-Q200 Grade 3, 0805", Cap_Case=0805, Manufacturer=MuRata, Supplier Part Number 1=490-12394-1-ND, TempCo=X5R, Tolerance_%=10%, Value1=Unknown, Value2=50V, ValueDisplayed=4.7uF
C109 C110: library part CMP-0007145-4, "CAP, CERM, 0.22 uF, 50 V, +/- 10%, X7R, AEC-Q200 Grade 1, 0603", Cap_Case=0603, Manufacturer=MuRata, Supplier Part Number 1=490-5402-1-ND, TempCo=X7R, Tolerance_%=10%, Value1=Unknown, Value2=50V, ValueDisplayed=0.22uF
C111 C300: library part CMP-0006849-4, "CAP, CERM, 0.01 uF, 25 V, +/- 5%, C0G/NP0, AEC-Q200 Grade 1, 0603", Cap_Case=0603, Manufacturer=Kemet, Supplier Part Number 1=399-14102-1-ND, TempCo=C0G/NP0, Tolerance_%=5%, Value1=Unknown, Value2=25V, ValueDisplayed=0.01uF
C112 C115 C301 C303 C304 C701: library part CMP-0076706-1, "CAP, CERM, 4.7 µF, 25 V,+/- 10%, X7R, AEC-Q200 Grade 1, 0805", Cap_Case=2x1.25x1.25mm, Manufacturer=TDK, Supplier Part Number 1=445-6967-1-ND, TempCo=X7R, Tolerance_%=10%, Value2=25V, ValueDisplayed=4.7µF
C114: library part CMP-0079607-1, "CAP, CERM, 1 µF, 16 V,+/- 10%, X7R, AEC-Q200 Grade 1, 0603", Cap_Case=0603, Manufacturer=TDK, Supplier Part Number 1=445-12539-1-ND, TempCo=X7R, Tolerance_%=10%, Value2=16V, ValueDisplayed=1µF
C302 C500 C501 C502 C503 C602 C800: library part CMP-0007106-4, "CAP, CERM, 0.1 uF, 16 V, +/- 10%, X7R, AEC-Q200 Grade 1, 0603", Cap_Case=0603, Manufacturer=TDK, Supplier Part Number 1=445-8136-1-ND, TempCo=X7R, Tolerance_%=10%, Value1=Unknown, Value2=16V, ValueDisplayed=0.1uF
C600 C601: library part CMP-0008021-2, "CAP, CERM, 0.1 uF, 50 V, +/- 10%, X7R, AEC-Q200 Grade 1, 0805", Cap_Case=0805, Manufacturer=MuRata, Supplier Part Number 1=490-8049-1-ND, TempCo=X7R, Tolerance_%=10%, Value1=Unknown, Value2=50V, ValueDisplayed=0.1uF
C900 C901 C902 C903: library part CMP-0007072-4, "CAP, CERM, 220 pF, 20 V, +/- 5%, C0G/NP0, AEC-Q200 Grade 1, 0603", Cap_Case=0603, Manufacturer=TDK, Supplier Part Number 1=445-5644-1-ND, TempCo=C0G/NP0, Tolerance_%=5%, Value1=Unknown, Value2=20V, ValueDisplayed=220pF
D100: library part CMP-0028785-1, "Diode, Schottky, 60 V, 3 A, AEC-Q101, SMA", Manufacturer="Diodes Inc.", Supplier Part Number 1=B360AM-13-FDICT-ND, Value1=3A, Value2=0.7V
D101: library part CMP-0005729-2, "Diode, TVS, Uni, 26 V, 42.1 Vc, AEC-Q101, SMC", Manufacturer=Littelfuse, Power_W=6.5W, Supplier Part Number 1=F6569CT-ND
D200: library part CMP-0080010-1, "Diode, Schottky, 100 V, 5 A, AEC-Q101, PowerDI5", Manufacturer="Diodes Inc.", Supplier Part Number 1=PDS5100HQ-13DICT-ND, Value1=5A, Value2=0.71V
D301 D700: library part CMP-0002944-2, "LED, Yellow, SMD", Color=yellow, Manufacturer=Kingbright, Supplier Part Number 1=754-1124-1-ND, Value1=W, Value2=2.5V
D302 D304 D306 D308 D310 D315 D316 D317 D318 D319: library part CMP-0067668-1, "LED, Red, SMD", Color=Red, Manufacturer=Vishay-Semiconductor, Power_TotalModule=200mW, Supplier Part Number 1=VLMR334BACB-GS08CT-ND, Value1=0.2W, Value2=2.2V
D303 D305 D307 D309 D311 D313: library part CMP-0003011-2, "LED, White, SMD", Color=White, Manufacturer=OSRAM, Supplier Part Number 1=475-2544-1-ND, Value1=W, Value2=3.2V
D312: library part CMP-0003012-2, "LED, Yellow, SMD", Color=Yellow, Manufacturer=OSRAM, Supplier Part Number 1=475-2562-1-ND, Value1=W, Value2=1.8V
D314: library part CMP-0003013-2, "LED, Blue, SMD", Color=Blue, Manufacturer=OSRAM, Supplier Part Number 1="LB T673-L2P1-25-Z-ND", Value1=W, Value2=3.1V
D900 D901: library part CMP-0029006-1, "Diode, Ultrafast, 100 V, 0.25 A, SOD-323", Manufacturer=Nexperia, Supplier Part Number 1=568-5003-1-ND, Value1=0.25A, Value2=1.4V
FID1 FID2 FID3: library part CMP-0077181-1, "Fiducial mark.  There is nothing to buy or mount.", Manufacturer=N/A
H1 H2 H3 H4: library part CMP-0003617-1, "Machine Screw, Round, #4-40 x 1/4, Nylon, Philips panhead", Manufacturer="B&F Fastener Supply", Supplier Part Number 1=H542-ND
J100: library part CMP-0055472-1, "Conn Term Block, 2POS, 3.81mm, TH", Manufacturer="Phoenix Contact", Supplier Part Number 1=277-1947-ND
J200: library part CMP-0055317-1, "Header, 100mil, 2x2, Tin, SMT", Manufacturer=Molex, Supplier Part Number 1=WM9514-ND
J700 J800: library part CMP-0055315-2, "Header, 100mil, 6x2, SMT", Manufacturer=Molex, Supplier Part Number 1=WM17452-ND
J900 J901: library part CMP-0065001-1, "Receptacle, 100mil, 10X2, Tin, TH", Manufacturer=FCI, Supplier Part Number 1=609-2274-ND
L100: library part CMP-0058945-1, "Inductor, Shielded, Metal Composite, 680 nH, 3.5 A, 0.03 ohm, AEC-Q200 Grade 1, SMD", Manufacturer="MuRata Toko", Value1="0.03 ohm", Value2=3.5A, ValueDisplayed=680nH
L101: library part CMP-0058942-1, "Inductor, Shielded, Metal Composite, 4.7 uH, 1.4 A, 0.165 ohm, AEC-Q200 Grade 1, SMD", Manufacturer="MuRata Toko", Value1="0.165 ohm", Value2=1.4A, ValueDisplayed=4.7uH
LBL1: library part CMP-0003625-1, "Thermal Transfer Printable Labels, 0.650\" W x 0.200\" H - 10,000 per roll", Manufacturer=Brady, Supplier Part Number 1=97C5133
Logo1: library part CMP-0074838-1, "Texas Instrument Corporate Signature"
Logo2: library part CMP-0074839-1
Logo3: library part CMP-0074847-1, "FCC_disclaimer"
NT100: library part CMP-0078142-2, "Single point connection between nets.", Manufacturer=N/A
R100: library part CMP-0025875-3, "RES, 100 k, 5%, 0.1 W, AEC-Q200 Grade 0, 0603", Manufacturer=Panasonic, Power_W=100mW, Supplier Part Number 1=P100KGCT-ND, TempCo="200 ppm/C", Tolerance_%=5%, Value2=0.1W, Value_Code=100k
R101 R300: library part CMP-0025701-4, "RES, 10 k, 5%, 0.1 W, AEC-Q200 Grade 0, 0603", Manufacturer=Vishay-Dale, Power_W=100mW, Supplier Part Number 1=541-10KGCT-ND, TempCo="200 ppm/C", Tolerance_%=5%, Value2=0.1W, Value_Code=10k0, ValueDisplayed=10k
R102: library part CMP-0022422-4, "RES, 43.2 k, 1%, 0.1 W, AEC-Q200 Grade 0, 0603", Manufacturer=Vishay-Dale, Power_W=100mW, Supplier Part Number 1=541-43.2KHCT-ND, TempCo="100 ppm/C", Tolerance_%=1%, Value2=0.1W, Value_Code=43k2, ValueDisplayed=43.2k
R200 R201 R203 R204 R302 R701 R900 R901: library part CMP-0025881-3, "RES, 4.7 k, 5%, 0.1 W, AEC-Q200 Grade 0, 0603", Manufacturer=Panasonic, Power_W=100mW, Supplier Part Number 1=P4.7KGCT-ND, TempCo="200 ppm/C", Tolerance_%=5%, Value2=0.1W, Value_Code=4k70, ValueDisplayed=4.7k
R202: library part CMP-0019338-2, "RES, 620, 0.5%, 0.1 W, 0805", Manufacturer="Susumu Co Ltd", Power_W=100mW, Supplier Part Number 1=RR12P620DCT-ND, TempCo="25 ppm/C", Tolerance_%=0.5%, Value2=0.1W, Value_Code=620R, ValueDisplayed=620
R301 R700 R906 R907 R908 R909: library part CMP-0025946-3, "RES, 1.0 k, 5%, 0.1 W, AEC-Q200 Grade 0, 0603", Manufacturer=Vishay-Dale, Power_W=100mW, Supplier Part Number 1=541-2213-1-ND, TempCo="200 ppm/C", Tolerance_%=5%, Value2=0.1W, Value_Code=1k00, ValueDisplayed=1.0k
R303: library part CMP-0022310-4, "RES, 2.43, 1%, 0.1 W, AEC-Q200 Grade 0, 0603", Manufacturer=Vishay-Dale, Power_W=100mW, Supplier Part Number 1=541-2.43HHCT-ND, TempCo="100 ppm/C", Tolerance_%=1%, Value2=0.1W, Value_Code=2R43, ValueDisplayed=2.43
R902: library part CMP-0025700-4, "RES, 100, 5%, 0.1 W, AEC-Q200 Grade 0, 0603", Manufacturer=Vishay-Dale, Power_W=100mW, Supplier Part Number 1=541-100GCT-ND, TempCo="200 ppm/C", Tolerance_%=5%, Value2=0.1W, Value_Code=100R, ValueDisplayed=100
R903: library part CMP-0020442-3, "RES, 0, 5%, 0.125 W, AEC-Q200 Grade 0, 0805", Manufacturer=Vishay-Dale, Power_W=125mW, Supplier Part Number 1=541-0.0ACT-ND, TempCo="200 ppm/C", Tolerance_%=5%, Value2=0.125W, Value_Code=0000, ValueDisplayed=0
TP100: library part CMP-0003825-1, "1mm Test Point, SMT", Manufacturer=Any
U100: library part CMP-0077180-4, "Automotive 65-V 0.6-A Synchronous Step-Down Converter, RNX0012B (VQFN-HR-12)", Alternate Manufacturer="Texas Instruments", Alternate PartNumber=LMR36006AQRNXTQ1
U200: library part CMP-0073689-2, "40V/100mOhm Single Channel Smart High Side Switch, PWP0014C (TSSOP-14)", Alternate Manufacturer="Texas Instruments"
U300: library part CMP-0078396-2, "Automotive Grade 16-Channel, Full Diagnostics, Constant-Current LED Driver with 7-Bit Dot Correction and 12-Bit PWM Dimming, DAP0038E (TSSOP-38)", Alternate Manufacturer="Texas Instruments"
U400: library part CMP-0074867-2, "Ambient Light Sensor (ALS), DNP0006A (USON-6)", Alternate Manufacturer="Texas Instruments", Alternate PartNumber=OPT3001IDNPTQ1
U500 U501 U502 U503: library part CMP-0081694-1, "High Accuracy 3.3 V or 5 V Ratiometric Bipolar Hall Effect Sensor Family, DBZ0003A (SOT-23-3)", Alternate Manufacturer="Texas Instruments", Alternate PartNumber=DRV5055A1QDBZR, Operating Temprature Range="-40 to 125 C", Rating=Catalog
U600: library part CMP-0066933-1, "50-mA 40-V Voltage-Tracking LDO With 5-mV Tracking Tolerance, DBV0005A (SOT-23-5)", Alternate Manufacturer="Texas Instruments"
U700: library part CMP-0081858-1, "Automotive Multi-Channel Half-Bridge Driver, PWP0024J (HTSSOP-24)", Alternate Manufacturer="Texas Instruments", Operating Temperature Range="-40 to 125 C", Rating=Automotive
U800: library part CMP-0066256-1, "Automotive Catalog 8-Channel Analog Multiplexer/Demultiplexer, PW0016A (TSSOP-16)", Alternate Manufacturer="Texas Instruments"
ZZ1: library part CMP-0003616-3
ZZ2: library part CMP-0077236-1
ZZ3: library part CMP-0077237-1
ZZ4: library part CMP-0077238-1

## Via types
v1: diameter 0.6, hole 0.3, Top Layer to Bottom Layer, 386 vias
v2: diameter 0.5, hole 0.2, Top Layer to Bottom Layer, tented both sides, 30 vias
v3: diameter 0.5, hole 0.2, Top Layer to Bottom Layer, 23 vias

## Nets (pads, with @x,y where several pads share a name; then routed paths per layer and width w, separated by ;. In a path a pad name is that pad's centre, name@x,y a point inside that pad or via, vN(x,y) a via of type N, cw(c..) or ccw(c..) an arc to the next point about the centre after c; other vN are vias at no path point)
/SCS: J901.18 U700.19 | length 142.6
  Signal Layer 2 w0.35: v1(23.419,17.399) 23.114,17.094 23.114,16.281 26.848,12.548 69.85,12.548 71.78,10.617 85.319,10.617 87.478,8.458 157.353,8.458 J901.18@158.623,7.188
  Bottom Layer w0.3: U700.19@23.246,19.402 23.246,17.572 v1(23.419,17.399)
/SLEEP: J901.20 U700.8 | length 152.3
  Signal Layer 2 w0.3: v1(26.34,28.778) 26.34,27.026 27.508,25.857 31.369,25.857 41.275,15.951 86.462,15.951 86.97,16.459 87.681,16.459 88.036,16.104 152.197,16.104 v1(152.908,15.392)
  Bottom Layer w0.3: v1(152.908,15.392) 152.908,8.052 155.042,5.918 157.378,5.918 J901.20@158.648,4.648
  Bottom Layer w0.35: U700.8@24.546,25.302 24.546,26.578 26.34,28.372 v1(26.34,28.778)
AGND: C114.1 NT100.1 R102.1 U100.6 | length 1.7
  Bottom Layer w0.3: U100.6@44.45,42.802 44.45,43.409 44.704,43.663 C114.1@44.704,44.348
BLANK: J901.11 U300.36 | length 79.8
  Top Layer w0.4: v1(123.088,19.888) 138.43,19.888 148.184,10.135 150.216,10.135 154.889,14.808 J901.11@156.108,14.808
  Signal Layer 1 w0.35: v1(86.462,20.93) 86.868,20.523 110.668,20.523 111.303,21.158 117.551,21.158 118.821,19.888 v1(123.088,19.888)
  Bottom Layer w0.35: U300.36@84.56,22.8 84.56,21.917 85.547,20.93 v1(86.462,20.93)
COS1: R907.2 U502.2 | length 103.1
  Top Layer w0.152: U502.2@17.998,39.66 U502.2@17.998,39.732
  Top Layer w0.4: U502.2@17.998,39.66 v1@18.796,38.862
  Signal Layer 2 w0.4: v1(18.795,38.862) 18.795,32.564 19.634,31.725 37.592,31.725 41.732,27.584 64.821,27.584 65.532,28.296 72.949,28.296 73.711,27.534 103.149,27.534 v1(105.131,25.552)
  Bottom Layer w0.5: v1(105.131,25.552) 105.131,21.527 R907.2@106.337,20.32
COS1_flt: C901.1 J900.8 R907.1 | length 8.4
  Bottom Layer w0.152: R907.1@107.937,20.32 R907.1@107.975,20.358
  Bottom Layer w0.3: R907.1@107.975,20.358 C901.1@109.88,20.358 110.681,21.158 114.198,21.158 J900.8@115.468,19.888
COS2: R909.2 U503.2 | length 56.1
  Top Layer w0.4: v1@167.107,34.544 167.274,34.376 U503.2@168.484,34.376
  Signal Layer 1 w0.152: v1@167.081,34.52 v1(167.105,34.544)
  Signal Layer 1 w0.5: v1(149.782,29.515) 164.567,29.515 167.081,32.029 v1@167.081,34.52
  Bottom Layer w0.5: R909.2@122.047,14.808 135.077,14.808 v1@149.784,29.515
COS2_flt: C903.1 J900.12 R909.1 | length 5
  Bottom Layer w0.152: J900.12@115.468,14.808 J900.12@115.481,14.796 ; C903.1@118.44,14.796 C903.1@118.453,14.808
  Bottom Layer w0.5: J900.12@115.481,14.796 C903.1@118.44,14.796 ; C903.1@118.453,14.808 R909.1@120.46,14.808
DC_OUT1: J700.1 U700.2 | length 10.9
  Bottom Layer w0.4: J700.1@11.747,28.753 18.161,28.753 20.646,26.268 U700.2@20.646,25.302
DC_OUT2: J700.2 U700.23 | length 24.6
  Signal Layer 1 w0.5: v1(4.42,27.381) 8.56,23.241 11.76,23.241 16.18,18.821 v1(17.323,18.821)
  Bottom Layer w0.45: v1(17.323,18.821) 18.11,18.034 20.142,18.034 20.646,18.538 U700.23@20.646,19.402
  Bottom Layer w0.5: v1(4.42,27.381) 5.791,28.753 J700.2@7.302,28.753
DC_OUT3: J700.3 U700.14 | length 21.9
  Signal Layer 1 w0.5: v1(17.755,20.777) 18.567,19.964 25.095,19.964 v1(27.076,17.983)
  Bottom Layer w0.4: U700.14@26.496,19.402 26.496,18.563 v1(27.076,17.983)
  Bottom Layer w0.5: J700.3@11.747,26.213 14.834,26.213 17.755,23.292 v1(17.755,20.777)
DC_OUT4: J700.4 U700.11 | length 28.7
  Signal Layer 1 w0.5: v1(9.525,27.534) 8.585,26.594 8.585,24.714 9.271,24.028 17.551,24.028 19.863,26.34 26.949,26.34 v1@27.584,26.975
  Bottom Layer w0.4: U700.11@26.496,25.302 26.496,26.115 27.356,26.975 v1(27.559,26.975)
  Bottom Layer w0.5: J700.4@7.302,26.213 8.204,26.213 v1(9.525,27.534)
DC_OUT5: J700.5 U700.3 | length 14
  Top Layer w0.5: v1(15.443,23.165) 16.129,23.851 16.535,23.851 17.069,24.384 17.069,24.917 v1(20.091,27.94)
  Bottom Layer w0.4: v1(20.091,27.94) 20.091,27.737 21.296,26.532 U700.3@21.296,25.302
  Bottom Layer w0.5: J700.5@11.747,23.673 14.935,23.673 v1(15.443,23.165)
DC_OUT6: J700.6 U700.10 | length 25.5
  Signal Layer 1 w0.5: v1(9.525,24.943) 10.49,25.908 17.958,25.908 19.202,27.153 25.629,27.153 26.264,27.788 v1(27.661,27.788)
  Bottom Layer w0.35: U700.10@25.846,25.302 25.846,26.303 27.33,27.788 v1(27.661,27.788)
  Bottom Layer w0.5: J700.6@7.302,23.673 8.255,23.673 v1(9.525,24.943)
DC_OUT7: J700.7 U700.4 | length 15.8
  Top Layer w0.5: v1(15.443,21.514) 15.443,21.565 17.882,24.003 17.882,24.384 21.006,27.508 v1(21.006,28.016)
  Bottom Layer w0.4: v1(21.006,28.016) 21.006,27.711 21.946,26.771 U700.4@21.946,25.302
  Bottom Layer w0.5: J700.7@11.747,21.133 15.062,21.133 v1(15.443,21.514)
DC_OUT8: J700.8 U700.22 | length 22.3
  Signal Layer 1 w0.5: v1(9.525,22.403) 8.026,20.904 8.026,19.329 9.042,18.313 13.487,18.313 14.783,17.018 v1(18.796,17.018)
  Bottom Layer w0.45: v1(18.796,17.018) 20.041,17.018 20.407,17.384 20.411,17.384 21.296,18.269 U700.22@21.296,19.402
  Bottom Layer w0.5: J700.8@7.302,21.133 8.255,21.133 v1(9.525,22.403)
DC_OUT9: J700.9 U700.9 | length 24.7
  Top Layer w0.5: v1(16.231,20.803) 18.72,23.292 18.72,23.774 21.819,26.873 25.603,26.873 27.33,28.6 v1(27.61,28.6)
  Bottom Layer w0.35: U700.9@25.196,25.302 25.196,26.415 25.296,26.515 25.296,26.531 27.365,28.6 v1(27.61,28.6)
  Bottom Layer w0.5: J700.9@11.747,18.593 14.021,18.593 v1(16.231,20.803)
DC_OUT10: J700.10 U700.15 | length 22.7
  Signal Layer 1 w0.5: v1(9.525,19.914) 13.64,19.914 15.57,17.983 19.66,17.983 20.701,19.025 24.943,19.025 v1(26.098,17.869)
  Bottom Layer w0.4: U700.15@25.846,19.402 25.846,18.121 v1(26.098,17.869)
  Bottom Layer w0.5: J700.10@7.302,18.593 8.204,18.593 v1(9.525,19.914)
DC_OUT11: J700.11 U700.17 | length 17.5
  Signal Layer 1 w0.5: v1(14.173,14.834) 19.761,14.834 20.574,15.646 24.079,15.646 24.714,16.281 24.714,16.993 v1(24.308,17.399)
  Bottom Layer w0.3: v1(24.308,17.399) 24.308,17.659 24.546,17.897 24.546,17.917 U700.17@24.546,19.402
  Bottom Layer w0.5: J700.11@11.747,16.053 12.954,16.053 v1(14.173,14.834)
DC_OUT12: J700.12 U700.18 | length 19.7
  Signal Layer 1 w0.5: v1(9.474,17.247) 13.233,17.247 14.376,16.104 19.329,16.104 21.392,18.166 v1(23.896,18.166)
  Bottom Layer w0.3: v1(23.896,18.166) U700.18@23.896,19.402
  Bottom Layer w0.5: J700.12@7.302,16.053 8.28,16.053 v1(9.474,17.247)
GCLK: J901.4 U300.4 U300.5 U300.6 | length 89.1
  Top Layer w0.3: v1(149.606,11.024) 153.822,15.24 153.822,22.631 154.889,23.698 157.378,23.698 J901.4@158.648,24.968
  Signal Layer 2 w0.3: v1(85.522,11.684) 110.211,11.684 110.871,11.024 v1(149.606,11.024)
  Bottom Layer w0.4: U300.6@82.61,15.3 U300.5@83.26,15.3 U300.4@83.91,15.3 83.91,13.296 v1(85.522,11.684)
GND: C103.2 C104.2 C105.2 C106.2 C107.2 C108.2 C109.2 C110.2 C111.2 C112.2 C113.2 C115.2 C300.2 C301.2 C302.2 C303.2 C304.2 C500.2 C501.2 C502.2 C503.2 C600.2 C601.2 C602.2 C700.2 C701.2 C702.2 C800.2 C900.2 C901.2 C902.2 C903.2 D101.2 D901.2 J100.2 J200.2 J200.4 J800.1 J800.2 J900.4 J901.2 NT100.2 R202.1 R303.1 U100.1 U100.11 U200.2 U200.15@100.076,37.287 U300.33 U300.37 U300.39 U400.2 U400.3 U400.7 U500.3 U501.3 U502.3 U503.3 U600.2 U600.5 U700.1 U700.13 U700.24 U700.25@23.571,22.352 U800.6 U800.7 U800.8 | length 48.8
  Top Layer w0.152: C501.2@160,41.623 C501.2@160.007,41.631 ; C503.2@170.32,33.426 C503.2@170.332,33.414
  Top Layer w0.3: U400.3@16.698,7.005 17.239,7.005 17.534,7.3 C300.2@18.237,7.3
  Top Layer w0.5: C500.2@14.364,36.678 14.364,35.166 15.145,34.385 U500.3@15.145,33.528 ; U502.3@18.948,37.332 20.136,37.332 20.917,38.113 C502.2@21.869,38.113 ; U501.3@160,37.332 C501.2@160,41.623 ; U503.3@166.084,33.426 C503.2@170.32,33.426
  Bottom Layer w0.5: J800.2@37.897,8.572 J800.1@37.897,13.018 37.897,15.621 38.202,15.926 U600.5@38.202,19.558
  Bottom Layer w0.8: C107.2@55.372,38.862 C106.2@57.975,38.862 C105.2@60.579,38.862 C104.2@63.182,38.862 69.266,38.862
  Bottom Layer w1: C108.2@48.514,38.862 C107.2@55.372,38.862
  other v1: 22.911,3.023 26.58,3.023 30.249,3.023 33.917,3.023 37.586,3.023 41.255,3.023 44.924,3.023 48.593,3.023 52.262,3.023 131.902,3.378 135.723,3.404 139.392,3.404 143.061,3.404 146.73,3.404 74.32,3.607 77.989,3.607 81.658,3.607 85.327,3.607 93.421,4.343 97.09,4.343 100.759,4.343 104.428,4.343 55.829,4.521 65.456,4.572 152.171,6.426 161.747,7.061 56.718,7.239 60.387,7.239 64.056,7.239 67.725,7.239 14.91,8.89 18.579,8.89 22.248,8.89 117.78,9.347 121.449,9.347 125.118,9.347 128.786,9.347 132.455,9.347 136.124,9.347 161.747,10.73 39.243,10.744 54.178,11.227 57.847,11.227 61.516,11.227 65.185,11.227 22.375,11.557 26.043,11.557 29.712,11.557 33.381,11.557 4.075,13.843 7.744,13.843 11.413,13.843 14.873,13.843 18.542,13.843 161.747,14.399 36.678,16.053 3.658,16.51 61.925,16.637 65.594,16.637 69.263,16.637 50.216,16.739 91.288,16.993 95.053,16.993 98.819,16.993 102.584,16.993 106.35,16.993 70.841,17.145 71.78,17.145 72.796,17.145 85.268,17.247 87.173,17.297 88.138,17.297 89.027,17.297 89.941,17.297 74.295,17.323 33.096,17.501 161.747,18.068 70.841,18.142 71.78,18.142 72.796,18.142 85.268,18.186 87.173,18.199 88.138,18.199 89.027,18.199 89.941,18.199 74.295,18.263 41.554,18.898 3.658,19.075 87.173,19.101 88.138,19.101 89.027,19.101 89.941,19.101 85.268,19.126 70.841,19.139 71.78,19.139 72.796,19.139 18.136,19.202 19.05,19.202 74.295,19.202 39.091,19.558 91.66,19.66 95.329,19.66 98.998,19.66 102.667,19.66 16.561,19.787 17.475,19.787 28.219,19.914 29.134,19.914 85.268,20.066 70.841,20.136 71.78,20.136 72.796,20.136 74.295,20.142 28.219,20.828 29.134,20.828 30.048,20.828 18.745,21.082 74.295,21.082 70.841,21.133 71.78,21.133 72.796,21.133 46.126,21.26 92.93,21.336 100.268,21.336 103.937,21.336 57.048,21.463 60.717,21.463 64.386,21.463 68.055,21.463 3.658,21.641 28.219,21.742 29.134,21.742 29.997,21.742 30.836,21.742 161.747,21.737 18.771,22.022 31.521,22.2 129.489,22.479 133.158,22.479 136.827,22.479 144.165,22.479 147.834,22.479 28.219,22.657 29.134,22.657 30.023,22.657 30.836,22.657 3.658,24.206 161.747,25.406 107.228,25.552 110.896,25.552 52.756,25.654 56.425,25.654 60.094,25.654 63.762,25.654 67.431,25.654 33.299,25.883 3.658,26.772 16.434,27.102 165.456,27.305 169.124,27.305 172.793,27.305 17.221,27.864 54.61,28.524 21.133,28.905 95.699,29.134 99.368,29.134 103.037,29.134 3.658,29.337 48.743,29.337 16.789,29.947 17.704,29.947 19.101,29.947 72.887,29.972 76.556,29.972 80.224,29.972 125.374,30.15 129.043,30.15 132.712,30.15 136.381,30.15 140.05,30.15 143.719,30.15 64.11,30.683 39.675,31.166 42.206,31.267 45.875,31.267 49.544,31.267 53.213,31.267 5.385,32.207 127.508,33.452 131.177,33.452 134.846,33.452 138.515,33.452 142.184,33.452 145.852,33.452 60.875,34.519 64.544,34.519 48.717,34.569 30.734,34.696 35.306,34.696 39.268,34.696 23.825,34.747 109.564,35.128 113.233,35.128 5.41,35.357 49.657,35.56 116.778,35.992 120.447,35.992 88.062,36.093 90.475,36.093 70.121,36.144 73.79,36.144 77.459,36.144 81.128,36.144 39.268,36.449 50.444,36.652 46.33,36.678 47.727,36.703 23.825,36.83 7.823,37.389 41.097,37.44 35.331,37.694 47.473,37.719 48.311,37.719 49.149,37.719 155.245,37.897 39.268,38.202 41.123,38.608 41.948,38.608 42.774,38.608 46.228,38.608 47.041,38.608 11.887,38.964 14.402,38.964 110.566,38.989 114.235,38.989 23.825,39.04 45.898,39.37 41.123,39.472 43.155,39.522 50.825,39.827 39.268,39.954 35.306,40.397 105.791,40.632 23.825,41.173 39.268,41.707 50.825,42.088 94.945,42.167 20.447,42.215 16.459,42.266 40.564,43.078 158.595,43.256 162.264,43.256 50.851,44.094 105.791,44.3 41.986,44.475 36.525,44.577 50.444,45.39 46.533,45.695 42.951,45.745 94.945,45.836 48.336,46.66 49.835,46.66 53.789,47.092 57.458,47.092 61.127,47.092 64.795,47.092 44.044,47.269 46.304,47.269 39.7,47.879 105.791,47.969
  other v2: 75.81,17.85 77.01,17.85 78.21,17.85 79.41,17.85 80.61,17.85 81.81,17.85 83.01,17.85 84.21,17.85 75.81,19.05 77.01,19.05 83.01,19.05 84.21,19.05 75.81,20.25 77.01,20.25 78.21,20.25 79.41,20.25 80.61,20.25 81.81,20.25 83.01,20.25 84.21,20.25 20.271,21.352 26.871,21.352 20.271,22.352 26.871,22.352 20.271,23.352 26.871,23.352 98.576,36.537 101.576,36.537 98.576,38.037 101.576,38.037
  other v3: 15.748,5.95 15.748,6.75 78.21,19.05 79.41,19.05 80.61,19.05 81.81,19.05 21.401,21.352 22.471,21.352 23.571,21.352 24.671,21.352 25.741,21.352 21.401,22.352 22.471,22.352 23.571,22.352 24.671,22.352 25.741,22.352 21.401,23.352 22.471,23.352 23.571,23.352 24.671,23.352 25.741,23.352 100.076,36.537 100.076,38.037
